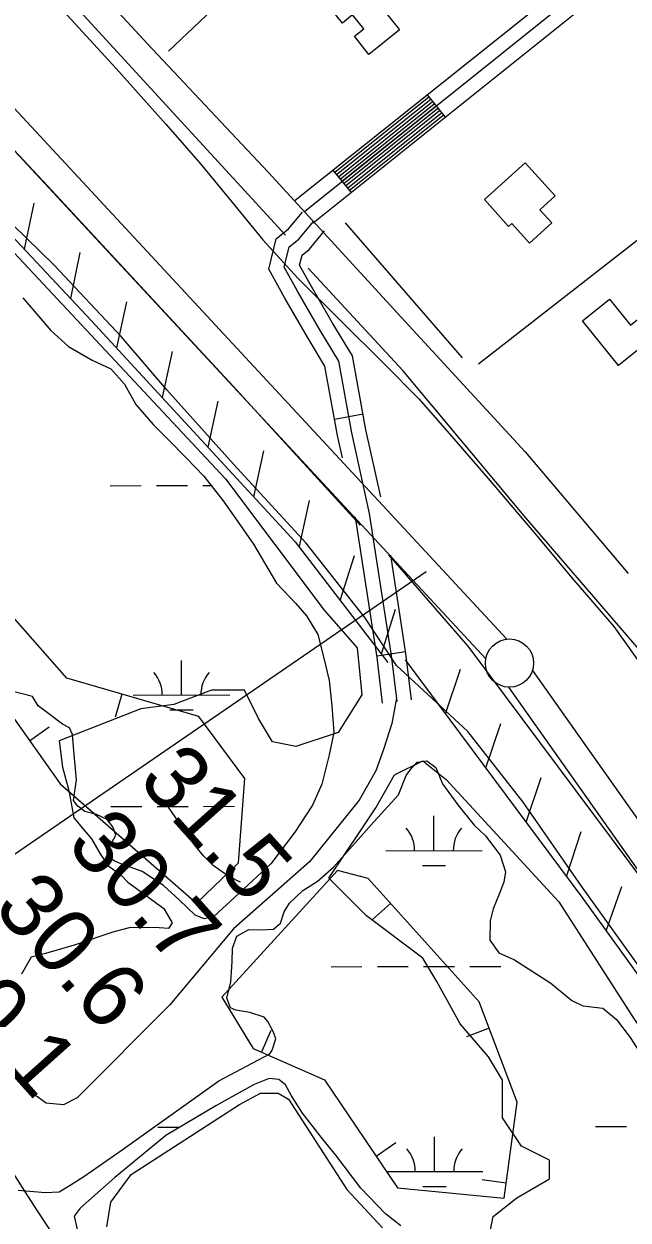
# Model space of a CAD drawing. Extents: x 3329332 to 3367211, y 631066 to 656469.
# Drawn here: x 3351483 to 3352109, y 641205 to 642445 of the extents above; entities that cross this region are included whole.
import ezdxf

# ---------------------------------------------------------------- set-up
doc = ezdxf.new("R2010")
doc.units = 0
for name, color, linetype in [('V-BLDG-OTLN', 7, 'Continuous'), ('V-BORW-LINE', 7, 'Continuous'), ('V-FLOD-BASE', 7, 'Continuous'), ('V-LEVE-TOET', 7, 'Continuous'), ('V-RIVR-EDGE', 7, 'Continuous'), ('V-RIVR-RANG', 7, 'Continuous'), ('V-ROAD-CNTR', 7, 'Continuous'), ('V-RRAP-FSHR', 7, 'Continuous'), ('V-SITE-VEGE', 7, 'Continuous'), ('V-SURV-LINE', 7, 'Continuous'), ('V-TOPO-MAJR', 7, 'Continuous'), ('V-TOPO-MINR', 7, 'Continuous'), ('V-TOPO-SHOR', 7, 'Continuous'), ('V-WETL-SWMP', 7, 'Continuous')]:
    doc.layers.add(name, color=color, linetype=linetype)

msp = doc.modelspace()

# ---------------------------------------------------------------- linework, layer by layer
at = {"layer": 'V-BLDG-OTLN'}
for points in [[(3351824.1, 642499.4), (3351872.5, 642438.6), (3351840.6, 642413.3), (3351825.7, 642432), (3351835.4, 642439.7), (3351823.8, 642454.2), (3351813.3, 642445.8), (3351791.4, 642473.4)], [(3352002.7, 642301), (3352033.9, 642266.6), (3352018, 642252.1), (3352030.3, 642238.5), (3352007.4, 642217.7), (3351989, 642238), (3351985.6, 642235), (3351960.5, 642262.7)], [(3352099.6, 642090.8), (3352062.2, 642137), (3352090.1, 642159.6), (3352111.9, 642132.6), (3352119.1, 642138.5), (3352134.7, 642119.2)]]:
    msp.add_lwpolyline(points, close=True, dxfattribs=at)
at = {"layer": 'V-BORW-LINE'}
for p, q in [((3351584.5, 641750.1), (3351577.5, 641726.1)), ((3351488.8, 641701.7), (3351509.2, 641716.2)), ((3351863.1, 641533), (3351844.5, 641516.2)), ((3351729.4, 641378.6), (3351739.5, 641401.5)), ((3351965.3, 641403.5), (3351942, 641394.6)), ((3351848.1, 641271), (3351868.8, 641285)), ((3351983.1, 641243.1), (3351958.3, 641246.5))]:
    msp.add_line(p, q, dxfattribs=at)
for points in [[(3351664.4, 641726.8), (3351527.5, 641766.7), (3351333.1, 641987), (3351182.1, 642177.7), (3351090.1, 642202.5), (3351207, 642037.2), (3351418.5, 641800.9), (3351520.5, 641657), (3351661.8, 641533.4), (3351705.6, 641575), (3351712, 641662.5), (3351664.4, 641726.8)], [(3351664.4, 641726.8), (3351527.5, 641766.7), (3351333.1, 641987), (3351223.3, 642125.7)], [(3351162.8, 642099.6), (3351207, 642037.2), (3351418.5, 641800.9), (3351520.5, 641657), (3351555.5, 641626.4)], [(3351701, 641677.4), (3351664.4, 641726.8)], [(3351808.3, 641567), (3351688.2, 641435.8), (3351720.6, 641382.6), (3351794.6, 641350), (3351870.4, 641238.1), (3351980.9, 641227.4), (3351994.6, 641326.8), (3351954.9, 641430.9), (3351839.9, 641558.7), (3351808.3, 641567)], [(3351712.7, 641395.5), (3351720.6, 641382.6), (3351794.6, 641350), (3351870.4, 641238.1), (3351980.9, 641227.4), (3351994.6, 641326.8), (3351954.9, 641430.9), (3351839.9, 641558.7), (3351829.4, 641561.5)]]:
    msp.add_lwpolyline(points, dxfattribs=at)
at = {"layer": 'V-FLOD-BASE'}
for points in [[(3351831.8, 641925.1), (3351700, 642069.2), (3351507.5, 642277), (3351293.5, 642505.9), (3351198.8, 642603.4), (3351125.5, 642685.2), (3351013.7, 642803.8), (3350818.1, 643002), (3350739.6, 643078.5), (3350700.3, 643111.6), (3350641.7, 643159.7), (3350528.2, 643250.7), (3350375.4, 643371), (3350158.1, 643542.5), (3350028.3, 643646.3), (3349793.8, 643819.4), (3349724, 643865.3), (3349578.5, 643961)], [(3352319.5, 641293.5), (3352307.1, 641312), (3352129.8, 641550.3), (3351943.5, 641799.8), (3351861.4, 641894.3)]]:
    msp.add_lwpolyline(points, dxfattribs=at)
at = {"layer": 'V-LEVE-TOET'}
for points in [[(3351869.5, 641779.7), (3351836.4, 641829.5), (3351775.7, 641906.6), (3351700.4, 641988.3), (3351631.3, 642065.4), (3351583.7, 642120.7), (3351514.5, 642194.7), (3351412.2, 642294.4), (3351245.5, 642471.2), (3351150.2, 642573.3), (3351081.8, 642644.9), (3351011.1, 642722.8), (3350880.5, 642863.8), (3350771.3, 642968.2), (3350691.3, 643043.8), (3350616.6, 643103.9), (3350554.3, 643155.4), (3350394.2, 643284.2), (3350311.8, 643355.9), (3350203.2, 643437.2), (3350110.1, 643516.7), (3349979.2, 643610.5), (3349872.1, 643694)], [(3351378.7, 642597.3), (3351516.3, 642466.3), (3351578.6, 642398.6), (3351630, 642341), (3351666.1, 642299.7), (3351698.4, 642260.8), (3351730.6, 642221.1), (3351767.2, 642181.2)], [(3351767.2, 642181.2), (3351855.9, 642093.3), (3351892.8, 642055.9), (3351928.9, 642014.7), (3351964.3, 641973.4), (3352013.4, 641915.8), (3352051, 641870.7), (3352094.8, 641820.1), (3352127.8, 641773.4), (3352200.6, 641673.8), (3352249.7, 641601.5), (3352304.1, 641523), (3352383, 641407.2), (3352472, 641280.4)], [(3352345.7, 641147.4), (3352305.9, 641208.8), (3352292.1, 641232.1), (3352266, 641268.6), (3352158.7, 641414.9), (3352061.3, 641550.9), (3352000.7, 641638), (3351943.2, 641711.2), (3351869.5, 641779.7)]]:
    msp.add_lwpolyline(points, dxfattribs=at)
at = {"layer": 'V-RIVR-EDGE'}
msp.add_spline([(3351880.4, 640440.2), (3351876.6, 640444.8), (3351875, 640453.8), (3351871.2, 640463.5), (3351865.8, 640470.1), (3351847.2, 640503.5), (3351818.7, 640553.6), (3351810.2, 640569.1), (3351795.9, 640585.8), (3351792.8, 640587.7), (3351786.2, 640594), (3351758.3, 640620.8), (3351741.3, 640637.5), (3351732.8, 640648.8), (3351730.5, 640655.4), (3351728.2, 640658.9), (3351720, 640667.4), (3351711.5, 640681), (3351709.6, 640686.5), (3351709.6, 640692.3), (3351709.3, 640702), (3351709.3, 640708.2), (3351711.6, 640715.5), (3351715.9, 640722.9), (3351717.5, 640736.1), (3351718.7, 640762.1), (3351717.2, 640778.3), (3351714.5, 640790.4), (3351713.4, 640790.8), (3351699.4, 640792), (3351689.7, 640796.3), (3351681.2, 640806), (3351671.2, 640818), (3351661.9, 640838.2), (3351651.1, 640851.4), (3351643, 640859.6), (3351631.3, 640865), (3351621.7, 640871.7), (3351610.8, 640881.4), (3351596.9, 640895.4), (3351584.5, 640905.1), (3351577.6, 640911.7), (3351552.8, 640932.3), (3351530.7, 640953.7), (3351519.1, 640964.2), (3351513.3, 640972), (3351507.2, 640987.1), (3351502.9, 640991), (3351492.8, 640996.8), (3351483.6, 641008.1), (3351471.6, 641031), (3351466.2, 641038), (3351459.2, 641043.9), (3351454.6, 641047), (3351449.5, 641056.3), (3351444.5, 641069.5), (3351431.4, 641103.3), (3351426.4, 641123), (3351423.7, 641129.3), (3351417.2, 641135.5), (3351411, 641147.1), (3351408.3, 641152.6), (3351407.1, 641154.1), (3351401.3, 641154.1), (3351396.7, 641158.8), (3351396.3, 641162.3), (3351398.2, 641164.6), (3351403.3, 641168.5), (3351403.3, 641173.5), (3351399.5, 641188.7), (3351394.8, 641192.2), (3351390.2, 641195.7), (3351385.9, 641202.6), (3351374.3, 641223.6), (3351352.3, 641258.2), (3351324.5, 641295.5), (3351308.2, 641315.3), (3351293.9, 641329.3), (3351280.8, 641344.8), (3351262.6, 641367), (3351248.7, 641388), (3351231.7, 641409.3), (3351211.2, 641433), (3351185.7, 641452.9), (3351174.1, 641464.9), (3351148.5, 641492.1), (3351129.6, 641514.3), (3351119.5, 641526.7), (3351108.7, 641542.3), (3351089, 641561.3), (3351069.2, 641578), (3351042.6, 641607.6), (3351001.9, 641654.6), (3350991.1, 641669.8), (3350979.1, 641683), (3350968.7, 641697.7), (3350957.9, 641718.3), (3350945.9, 641745.1), (3350930.1, 641774.2), (3350917.7, 641788.2), (3350908.9, 641801.4), (3350900.7, 641814.6), (3350886.8, 641828.2), (3350867.5, 641850.4), (3350846.2, 641866), (3350833.8, 641880.3), (3350825.7, 641891.2), (3350823.8, 641901.3), (3350821.9, 641913.3), (3350814.5, 641925.8), (3350807.2, 641935.1), (3350774.3, 641956.1), (3350737.1, 641982.2), (3350728.2, 641990.7), (3350716.6, 642008.2), (3350699.6, 642028), (3350681.4, 642049.4), (3350672.5, 642061.5), (3350666, 642077), (3350661.8, 642091), (3350651.3, 642098.7), (3350621.1, 642117.4), (3350608.7, 642131), (3350602.2, 642140.4), (3350596.4, 642145), (3350579.7, 642150.5), (3350575.4, 642153.6), (3350553.4, 642176.2), (3350549.1, 642181.2), (3350546.4, 642189.4), (3350542.2, 642195.2), (3350532.1, 642204.9), (3350519.8, 642218.9), (3350511.2, 642226.3), (3350489.2, 642235.6), (3350466.3, 642247.7), (3350456.2, 642257.1), (3350446.2, 642269.5), (3350443.5, 642279.2), (3350448.2, 642287.7), (3350448.6, 642299), (3350443.2, 642308.3), (3350432, 642318.8), (3350419.2, 642325.4), (3350405.6, 642329.7), (3350394, 642331.7), (3350385.1, 642332.1), (3350382.4, 642334.8), (3350380.4, 642339.5), (3350380.1, 642346.8), (3350385.1, 642354.6), (3350386.7, 642361.9), (3350384, 642369.3), (3350373.6, 642391.4), (3350360.4, 642400.4), (3350342.6, 642404.7), (3350325.9, 642404.7), (3350320.1, 642403.2), (3350313.9, 642402.4), (3350303.8, 642408.7), (3350298.8, 642411.8), (3350296.5, 642416.8), (3350298.4, 642426.1), (3350307, 642442.8), (3350316.8, 642460.6), (3350320.3, 642463.7), (3350322.2, 642467.2), (3350321.4, 642477.3), (3350312.9, 642488.2), (3350302.1, 642494.4), (3350278.1, 642501), (3350262.2, 642505.7), (3350248.6, 642515.5), (3350230.8, 642536.4), (3350216.2, 642559.4)], degree=3, dxfattribs=at)
at = {"layer": 'V-RIVR-RANG'}
msp.add_line((3351900.2, 641876.8), (3350691.2, 641047.6), dxfattribs=at)
at = {"layer": 'V-ROAD-CNTR'}
for p, q in [((3351901, 642371.5), (3351919.8, 642348.1)), ((3351803.4, 642293.4), (3351822.2, 642270)), ((3351805.2, 642035.1), (3351834.7, 642040.5)), ((3351849.2, 641789.6), (3351878.8, 641794.2))]:
    msp.add_line(p, q, dxfattribs=at)
for points in [[(3351042.6, 643027.6), (3351243.5, 642821.1), (3351388.9, 642664.9), (3351610.8, 642424.6), (3351736.4, 642291.2), (3351874.3, 642140.8), (3352002.6, 642001.1), (3352109.5, 641875)], [(3351764.4, 642262.1), (3352037.5, 642480.7), (3352229.1, 642628.1)], [(3351783.1, 642238.7), (3352056, 642457.1), (3352262.5, 642615.9), (3352298.1, 642614.6), (3352342.1, 642600.8), (3352380.2, 642572.6), (3352420.2, 642536.5), (3352461.9, 642491.7), (3352495.1, 642473.5), (3352513.9, 642471.1), (3352549, 642469.2), (3352609.3, 642494.1), (3352632.2, 642507.1), (3352723, 642585.5), (3352748.9, 642604.6), (3352749.2, 642604.8)], [(3351773.8, 642250.4), (3352046.8, 642468.9)], [(3351805.3, 642291), (3351902.9, 642369.1)], [(3351807.2, 642288.7), (3351904.8, 642366.8)], [(3351809.1, 642286.4), (3351906.7, 642364.5)], [(3351810.9, 642284), (3351908.5, 642362.1)], [(3351812.8, 642281.7), (3351910.4, 642359.8)], [(3351814.7, 642279.3), (3351912.3, 642357.4)], [(3351816.6, 642277), (3351914.1, 642355.1)], [(3351818.4, 642274.6), (3351916, 642352.8)], [(3351820.3, 642272.3), (3351917.9, 642350.4)], [(3351813.4, 641994.9), (3351808.3, 642018), (3351795.1, 642089.9), (3351776.9, 642120.1), (3351753.7, 642160.4), (3351736.9, 642190.6), (3351744.7, 642222.1), (3351757.5, 642232.4), (3351771.8, 642249.6)], [(3351869.9, 641742.2), (3351864.3, 641790), (3351841.5, 641937.4), (3351823, 642020.9), (3351809.4, 642095.3), (3351789.8, 642127.8), (3351766.7, 642167.8), (3351752.9, 642192.8), (3351758, 642213.6), (3351768.1, 642221.7), (3351783.3, 642240)], [(3351853, 641954.5), (3351837.7, 642023.9), (3351823.7, 642100.7), (3351802.7, 642135.4), (3351779.8, 642175.2), (3351768.9, 642194.9), (3351771.4, 642205.1), (3351778.7, 642211), (3351794.8, 642230.5)], [(3351855, 641740.5), (3351849.4, 641788), (3351826.9, 641933.6)], [(3351884.8, 641744), (3351879.1, 641792.1), (3351863.4, 641893.9)], [(3351869.2, 641745.9), (3351869.2, 641745.7), (3351864.6, 641719.6), (3351856.2, 641693.5), (3351847.8, 641670.4), (3351830.5, 641640), (3351779.3, 641576.1), (3351700.5, 641506.5), (3351634.3, 641427.9), (3351538.1, 641331.5), (3351523.9, 641324.2), (3351506, 641325.8), (3351492.7, 641335.6), (3351434.2, 641415.8)]]:
    msp.add_lwpolyline(points, dxfattribs=at)
at = {"layer": 'V-RRAP-FSHR'}
for p, q in [((3351483.6, 642211.3), (3351493.6, 642259.1)), ((3351531.5, 642160.2), (3351541.5, 642208)), ((3351579.2, 642109), (3351589.6, 642156.7)), ((3351626.6, 642057.5), (3351637, 642105.2)), ((3351674, 642006), (3351684.5, 642053.7)), ((3351721.4, 641954.5), (3351731.9, 642002.2)), ((3351768.9, 641903), (3351779.3, 641950.7)), ((3351811, 641847.1), (3351825.7, 641893.7)), ((3351853.7, 641791.6), (3351868.3, 641838.2)), ((3351920.3, 641729.5), (3351935.6, 641775.9)), ((3351962, 641673.4), (3351977.4, 641719.7)), ((3352003.8, 641617.2), (3352019.2, 641663.5)), ((3352045.6, 641561), (3352061, 641607.4)), ((3352086.9, 641504.5), (3352103, 641550.6))]:
    msp.add_line(p, q, dxfattribs=at)
for points in [[(3349424.9, 643987.3), (3349682.6, 643818.4), (3349816.4, 643731.1), (3349921.1, 643649.1), (3350310.3, 643344.4), (3350572.5, 643138.1), (3350703, 643034.6), (3350964.8, 642768.6), (3351214.5, 642498.2), (3351553.2, 642137.1), (3351764.3, 641908), (3351860.4, 641782.9)], [(3350010.2, 643579.4), (3350310.3, 643344.4), (3350572.5, 643138.1), (3350703, 643034.6), (3350964.8, 642768.6), (3351214.5, 642498.2), (3351553.2, 642137.1), (3351764.3, 641908), (3351860.4, 641782.9)], [(3351878.5, 641785.7), (3352062.7, 641538.1), (3352285.1, 641229.4)]]:
    msp.add_lwpolyline(points, dxfattribs=at)
at = {"layer": 'V-SITE-VEGE'}
for points in [[(3351258.7, 642436.3), (3351692.1, 641973.3), (3351794.3, 641836.9), (3351828.4, 641797.9), (3351833.3, 641749.2), (3351808.9, 641710.2), (3351765.1, 641695.6), (3351740.8, 641700.4), (3351726.2, 641724.8), (3351711.6, 641754), (3351677.5, 641754), (3351638.5, 641739.4), (3351604.4, 641734.6), (3351519.5, 641701.7), (3351523, 641674.1), (3351529.6, 641650.2), (3351534.6, 641621.8), (3351547.2, 641606.8), (3351553.1, 641600), (3351562, 641584.3), (3351570.1, 641572.3), (3351583.5, 641562.5), (3351590.9, 641555), (3351628, 641527.9), (3351636.8, 641512.9), (3351633.1, 641507), (3351623.4, 641507.8), (3351593.5, 641508), (3351576.4, 641503.6), (3351535.2, 641489.7), (3351505.3, 641481), (3351490.4, 641477.3), (3351480.6, 641459.5)], [(3351964.8, 641183.9), (3351969.6, 641208.3), (3351994, 641227.8), (3352028.1, 641247.3), (3352028.1, 641266.7), (3351998.8, 641281.4), (3351979.4, 641310.6), (3351979.4, 641349.6), (3351964.8, 641374), (3351935.5, 641408.1), (3351911.2, 641451.9), (3351896.6, 641476.3), (3351838.2, 641520.1), (3351799.2, 641559.1), (3351847.9, 641632.2), (3351867.4, 641666.3), (3351896.6, 641681), (3351920.9, 641661.5), (3352037.8, 641534.8), (3352115.7, 641412.9), (3352227.7, 641257), (3352310.5, 641140.1)], [(3351569.1, 641197.8), (3351573, 641223.1), (3351594.1, 641252.1), (3351706.5, 641324.5), (3351728.2, 641336.2), (3351746.8, 641336.1), (3351757.2, 641330.1), (3351817.8, 641236.4), (3351854.8, 641196.6)]]:
    msp.add_lwpolyline(points, dxfattribs=at)
at = {"layer": 'V-SURV-LINE'}
for points in [[(3351081.7, 642779.1), (3351983.9, 641807.1)], [(3351961.9, 641786.7), (3351059.7, 642758.7)], [(3352010.3, 641774.6), (3352528.2, 641042.2)], [(3352503.7, 641024.9), (3351985.8, 641757.2)]]:
    msp.add_lwpolyline(points, dxfattribs=at)
msp.add_circle((3351986.5, 641782.2), 25, dxfattribs=at)
at = {"layer": 'V-TOPO-MAJR'}
msp.add_lwpolyline([(3351664.9, 640959.9), (3351497.1, 641214.2), (3351483.9, 641234.7), (3351470.9, 641255.4)], dxfattribs=at)
at = {"layer": 'V-TOPO-MINR'}
msp.add_lwpolyline([(3351707.7, 641555), (3351703.9, 641556.7), (3351691.1, 641563.9), (3351679.3, 641572.2), (3351669.1, 641582.4), (3351659.8, 641593.8), (3351629.9, 641637.4)], dxfattribs=at)
at = {"layer": 'V-TOPO-SHOR'}
msp.add_line((3351816, 642238.7), (3351937.4, 642098.6), dxfattribs=at)
for points in [[(3351754.4, 642225.8), (3351319.9, 642698.9), (3351115.5, 642913.2), (3350972.8, 643055.4), (3350842.9, 643180.5), (3350723.7, 643282.3), (3350596, 643384.1), (3350363.9, 643575), (3350095.7, 643782.8), (3349963.8, 643882.4), (3349812.7, 643984.1)], [(3351632.8, 642416.7), (3351691, 642471.8), (3351820.7, 642577.5), (3351980.6, 642714.6)], [(3351954.5, 642092.3), (3352336.5, 642390.5), (3352381.1, 642424.6)], [(3352449, 641349.3), (3352191.1, 641703.7), (3352129.3, 641786.5), (3352003.6, 641932.9), (3351875.8, 642085.7), (3351777.9, 642191.8)]]:
    msp.add_lwpolyline(points, dxfattribs=at)
at = {"layer": 'V-WETL-SWMP'}
for p, q in [((3351572.6, 641966.1), (3351604.6, 641966.2)), ((3351620.6, 641966.2), (3351652.6, 641966.3)), ((3351668.6, 641966.3), (3351677.1, 641966.3)), ((3351646.4, 641749), (3351646.3, 641785)), ((3351596.4, 641748.9), (3351696.4, 641749.1)), ((3351634.4, 641733.6), (3351658.4, 641733.6)), ((3351573.2, 641633.5), (3351605.2, 641633.5)), ((3351621.2, 641633.6), (3351653.2, 641633.6)), ((3351669.2, 641633.6), (3351701.2, 641633.7)), ((3351908.2, 641587.7), (3351908.1, 641623.7)), ((3351858.2, 641587.6), (3351958.2, 641587.8)), ((3351896.2, 641572.2), (3351920.2, 641572.3)), ((3351801.5, 641467.4), (3351833.5, 641467.5)), ((3351849.5, 641467.5), (3351881.5, 641467.5)), ((3351897.5, 641467.6), (3351929.5, 641467.6)), ((3351945.5, 641467.7), (3351977.5, 641467.7)), ((3351621.9, 641300.9), (3351644.5, 641300.9)), ((3352075.8, 641301.7), (3352107.8, 641301.8)), ((3351908.8, 641255), (3351908.7, 641291)), ((3351858.8, 641254.9), (3351958.8, 641255.1)), ((3351896.8, 641239.5), (3351920.8, 641239.6))]:
    msp.add_line(p, q, dxfattribs=at)
for points in [[(3351481.9, 642160.8), (3351510.8, 642127.1), (3351529.4, 642110.5), (3351553.9, 642096.2), (3351573.2, 642087.1), (3351587.3, 642071.3), (3351599.1, 642050.4), (3351616.9, 642029.4), (3351632.4, 642014.3), (3351651.7, 641994.8), (3351669.5, 641976), (3351689.5, 641950.5), (3351702.8, 641931.8), (3351721.2, 641905.5), (3351744.8, 641865.1), (3351764.8, 641844.1), (3351776, 641831.3), (3351787.8, 641811.8), (3351793.6, 641788.7), (3351799.4, 641764), (3351802.2, 641737.9), (3351804.2, 641710.2), (3351799.6, 641687.1), (3351791.9, 641656.6), (3351782.1, 641635), (3351764, 641606.8), (3351739.2, 641574.1), (3351706.1, 641543.7), (3351679.8, 641519.3), (3351670.1, 641517.1), (3351660.5, 641520.9), (3351644.1, 641536.7), (3351627.8, 641551.7), (3351605.5, 641566.1), (3351584.7, 641573.7), (3351577.3, 641576.7), (3351570.6, 641580.5), (3351572.1, 641592.4), (3351578.2, 641603.6), (3351575.3, 641612.5), (3351569.3, 641620), (3351558.2, 641625.3), (3351546.3, 641628.4), (3351538.8, 641633.7), (3351534.4, 641639.7), (3351537.5, 641661.3), (3351534.7, 641691.1), (3351533.4, 641708.3), (3351530.4, 641715.1), (3351523, 641718.8), (3351508.9, 641729.4), (3351497.8, 641737.7), (3351491.8, 641747.4), (3351456.8, 641756.6)], [(3351476.9, 641235.7), (3351505.5, 641233.2), (3351519.5, 641233.9), (3351531.1, 641240.8), (3351545.1, 641250), (3351584.8, 641277.6), (3351685.1, 641348.9), (3351737.9, 641377.1), (3351740.3, 641381), (3351744.2, 641392.6), (3351741.9, 641399.6), (3351735.8, 641410.4), (3351732, 641415.1), (3351717.3, 641419.9), (3351702.6, 641422.3), (3351697.2, 641424.6), (3351693.4, 641434.7), (3351697.4, 641451.7), (3351699.1, 641472.6), (3351699.2, 641486.5), (3351703.9, 641498.9), (3351716.3, 641505.8), (3351729.5, 641505.7), (3351741.9, 641506.4), (3351748.9, 641512.5), (3351752.8, 641524.1), (3351758.3, 641533.3), (3351772.3, 641546.4), (3351787.1, 641555.6), (3351804.2, 641571), (3351846.3, 641617.9), (3351871.3, 641645.6), (3351879.2, 641665.7), (3351885.4, 641673.4), (3351890.9, 641679.5), (3351900.9, 641681), (3351910.2, 641674), (3351917, 641656.9), (3351933.1, 641635.1), (3351950, 641614.1), (3351961.6, 641603.2), (3351976.9, 641583), (3351982.2, 641565.9), (3351980.6, 641555.1), (3351975.9, 641542.7), (3351969.6, 641527.3), (3351966.4, 641514.9)], [(3351966.4, 641514.9), (3351966.2, 641494.8), (3351975.4, 641481.6), (3351991.6, 641474.5), (3352029.4, 641450.3), (3352051, 641432.3), (3352062.5, 641426.8), (3352083.4, 641424.4), (3352097.3, 641412.7), (3352111.8, 641394), (3352128.7, 641367.6), (3352151.7, 641337.2), (3352167.9, 641326.3), (3352192.6, 641309.9), (3352232.5, 641269.3), (3352236.4, 641263.1), (3352238.6, 641252.3), (3352241.6, 641233.7), (3352240.7, 641219), (3352245.3, 641208.1), (3352258.3, 641191)], [(3351874, 641198.7), (3351857.9, 641211.2), (3351832.5, 641237.7), (3351806.4, 641271.9), (3351792.6, 641289), (3351771.9, 641315.5), (3351760.4, 641333.4), (3351754.3, 641345), (3351747.3, 641350.5), (3351737.3, 641351.3), (3351721.8, 641345.2), (3351702.3, 641334.5), (3351682.1, 641323.1), (3351630.1, 641292.5), (3351577.2, 641248.7), (3351541.3, 641217.2), (3351535.1, 641208.7), (3351538.1, 641194.8)]]:
    msp.add_lwpolyline(points, dxfattribs=at)
for centre, start, end in [((3351591.2, 641749.4), 359.3365, 40.8801), ((3351701.7, 641749.6), 139.3365, 180.8801), ((3351852.9, 641588), 359.3365, 40.8801), ((3351963.4, 641588.2), 139.3365, 180.8801), ((3351853.5, 641255.4), 359.3365, 40.8801), ((3351964, 641255.6), 139.3365, 180.8801)]:
    msp.add_arc(centre, 35.2, start, end, dxfattribs=at)

# ---------------------------------------------------------------- texts
at = {"layer": 'V-RIVR-RANG'}
for s, p in [('31.5', (3351600, 641659.9)), ('30.7', (3351525.7, 641593)), ('30.6', (3351450.1, 641527.5)), ('30.1', (3351378.6, 641457.5))]:
    msp.add_text(s, height=67, rotation=311.8383, dxfattribs=at).set_placement(p)

doc.saveas('drawing.dxf')
